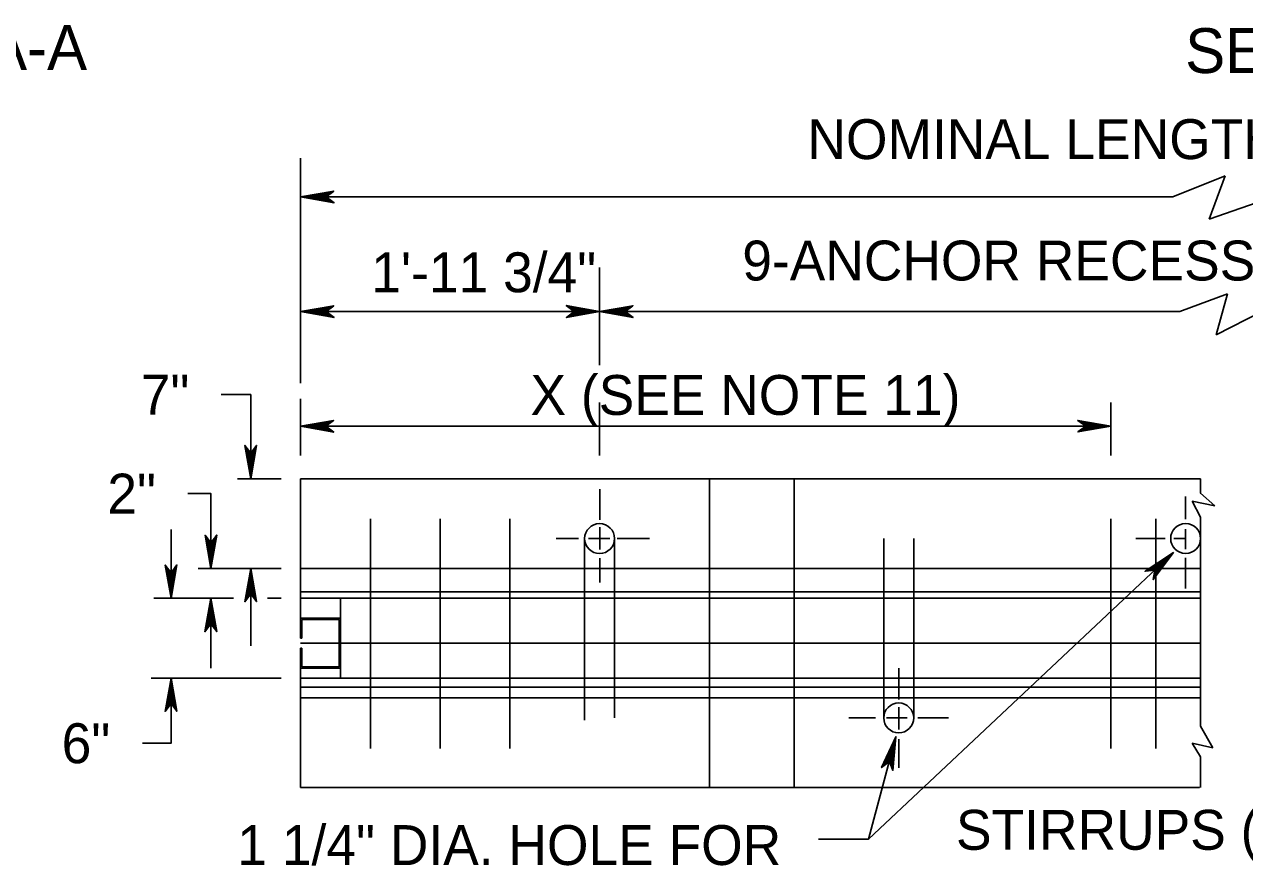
# Model space of a CAD drawing. Extents: x 499866 to 500993, y 499985 to 500645.
# Drawn here: x 500238.9 to 500361.2, y 500209.8 to 500294.1 of the extents above; entities that cross this region are included whole.
import ezdxf

# ---------------------------------------------------------------- set-up
doc = ezdxf.new("R2010")
doc.units = 0
doc.layers.add('24', color=7, linetype='Continuous')
doc.layers.add('5', color=7, linetype='Continuous')

msp = doc.modelspace()

# ---------------------------------------------------------------- linework, layer by layer
at = {"layer": '24'}
for points in [[(500266.6, 500276.85), (500269.95, 500276.25), (500269.15, 500276.85), (500269.93, 500277.43), (500266.6, 500276.85), (500266.82, 500276.85), (500269.85, 500276.3), (500269.09, 500276.85), (500269.8, 500277.38), (500266.94, 500276.86), (500267.05, 500276.85), (500269.65, 500276.38), (500269.07, 500276.85), (500269.67, 500277.31), (500267.1, 500276.85), (500267.21, 500276.86), (500269.49, 500276.45), (500269.04, 500276.85), (500269.5, 500277.25), (500267.54, 500276.86), (500267.73, 500276.86), (500269.32, 500276.54), (500269.01, 500276.84), (500269.34, 500277.17), (500267.76, 500276.85), (500267.94, 500276.84), (500269.14, 500276.63), (500268.91, 500276.86), (500269.16, 500277.09), (500268.1, 500276.85), (500268.27, 500276.83), (500268.99, 500276.69), (500268.87, 500276.85), (500269.07, 500277.03), (500268.36, 500276.85), (500268.83, 500276.73), (500268.76, 500276.86), (500268.97, 500276.99), (500268.48, 500276.86), (500268.79, 500276.79), (500268.66, 500276.89), (500268.8, 500276.95), (500268.66, 500276.85), (500268.73, 500276.84)], [(500266.6, 500265.35), (500269.95, 500264.75), (500269.15, 500265.35), (500269.93, 500265.93), (500266.6, 500265.35), (500266.82, 500265.35), (500269.85, 500264.8), (500269.09, 500265.35), (500269.8, 500265.88), (500266.94, 500265.36), (500267.05, 500265.35), (500269.65, 500264.88), (500269.07, 500265.35), (500269.67, 500265.81), (500267.1, 500265.35), (500267.21, 500265.36), (500269.49, 500264.95), (500269.04, 500265.35), (500269.5, 500265.75), (500267.54, 500265.36), (500267.73, 500265.36), (500269.32, 500265.04), (500269.01, 500265.34), (500269.34, 500265.67), (500267.76, 500265.35), (500267.94, 500265.34), (500269.14, 500265.13), (500268.91, 500265.36), (500269.16, 500265.59), (500268.1, 500265.35), (500268.27, 500265.33), (500268.99, 500265.19), (500268.87, 500265.35), (500269.07, 500265.53), (500268.36, 500265.35), (500268.83, 500265.23), (500268.76, 500265.36), (500268.97, 500265.49), (500268.48, 500265.36), (500268.79, 500265.29), (500268.66, 500265.39), (500268.8, 500265.45), (500268.66, 500265.35), (500268.73, 500265.34)], [(500296.57, 500265.35), (500293.22, 500265.94), (500294.02, 500265.35), (500293.24, 500264.76), (500296.57, 500265.35), (500296.35, 500265.34), (500293.31, 500265.89), (500294.08, 500265.34), (500293.37, 500264.81), (500296.23, 500265.33), (500296.11, 500265.35), (500293.52, 500265.81), (500294.1, 500265.34), (500293.5, 500264.88), (500296.06, 500265.35), (500295.95, 500265.33), (500293.68, 500265.74), (500294.12, 500265.35), (500293.67, 500264.94), (500295.63, 500265.33), (500295.44, 500265.33), (500293.85, 500265.66), (500294.16, 500265.36), (500293.83, 500265.02), (500295.41, 500265.35), (500295.23, 500265.36), (500294.03, 500265.56), (500294.26, 500265.33), (500294.01, 500265.1), (500295.06, 500265.35), (500294.89, 500265.36), (500294.18, 500265.5), (500294.29, 500265.34), (500294.1, 500265.16), (500294.81, 500265.35), (500294.34, 500265.46), (500294.41, 500265.33), (500294.2, 500265.2), (500294.69, 500265.33), (500294.38, 500265.41), (500294.51, 500265.31), (500294.36, 500265.24), (500294.51, 500265.34), (500294.43, 500265.36)], [(500296.57, 500265.35), (500299.92, 500264.75), (500299.12, 500265.35), (500299.9, 500265.93), (500296.57, 500265.35), (500296.79, 500265.35), (500299.83, 500264.8), (500299.06, 500265.35), (500299.77, 500265.88), (500296.91, 500265.36), (500297.02, 500265.35), (500299.62, 500264.88), (500299.04, 500265.35), (500299.64, 500265.81), (500297.07, 500265.35), (500297.19, 500265.36), (500299.46, 500264.95), (500299.02, 500265.35), (500299.47, 500265.75), (500297.51, 500265.36), (500297.7, 500265.36), (500299.29, 500265.04), (500298.98, 500265.34), (500299.31, 500265.67), (500297.73, 500265.35), (500297.91, 500265.34), (500299.11, 500265.13), (500298.88, 500265.36), (500299.13, 500265.59), (500298.07, 500265.35), (500298.24, 500265.33), (500298.96, 500265.19), (500298.84, 500265.35), (500299.04, 500265.53), (500298.33, 500265.35), (500298.8, 500265.23), (500298.73, 500265.36), (500298.94, 500265.49), (500298.45, 500265.36), (500298.76, 500265.29), (500298.63, 500265.39), (500298.78, 500265.45), (500298.63, 500265.35), (500298.71, 500265.34)], [(500266.6, 500253.85), (500269.92, 500253.26), (500269.13, 500253.85), (500269.91, 500254.42), (500266.6, 500253.85), (500266.82, 500253.85), (500269.83, 500253.3), (500269.07, 500253.85), (500269.77, 500254.38), (500266.94, 500253.86), (500267.05, 500253.85), (500269.63, 500253.39), (500269.05, 500253.85), (500269.64, 500254.3), (500267.1, 500253.85), (500267.21, 500253.86), (500269.46, 500253.46), (500269.03, 500253.85), (500269.47, 500254.25), (500267.53, 500253.86), (500267.72, 500253.86), (500269.3, 500253.54), (500268.99, 500253.84), (500269.32, 500254.17), (500267.75, 500253.85), (500267.93, 500253.84), (500269.12, 500253.63), (500268.89, 500253.86), (500269.14, 500254.09), (500268.09, 500253.85), (500268.26, 500253.83), (500268.97, 500253.69), (500268.86, 500253.85), (500269.05, 500254.03), (500268.35, 500253.85), (500268.81, 500253.74), (500268.74, 500253.86), (500268.95, 500253.99), (500268.46, 500253.86), (500268.77, 500253.79), (500268.64, 500253.89), (500268.79, 500253.95), (500268.64, 500253.85), (500268.72, 500253.84)], [(500347.82, 500253.85), (500344.49, 500254.43), (500345.29, 500253.85), (500344.51, 500253.27), (500347.82, 500253.85), (500347.59, 500253.84), (500344.58, 500254.39), (500345.35, 500253.84), (500344.64, 500253.31), (500347.48, 500253.83), (500347.37, 500253.85), (500344.79, 500254.3), (500345.37, 500253.84), (500344.77, 500253.39), (500347.31, 500253.85), (500347.2, 500253.83), (500344.95, 500254.24), (500345.39, 500253.85), (500344.94, 500253.44), (500346.88, 500253.83), (500346.7, 500253.83), (500345.12, 500254.15), (500345.42, 500253.86), (500345.09, 500253.52), (500346.66, 500253.85), (500346.48, 500253.86), (500345.3, 500254.06), (500345.53, 500253.83), (500345.28, 500253.6), (500346.32, 500253.85), (500346.15, 500253.86), (500345.44, 500254), (500345.56, 500253.84), (500345.36, 500253.66), (500346.07, 500253.85), (500345.6, 500253.96), (500345.67, 500253.83), (500345.47, 500253.7), (500345.95, 500253.83), (500345.65, 500253.91), (500345.77, 500253.81), (500345.63, 500253.75), (500345.77, 500253.84), (500345.7, 500253.86)], [(500261.6, 500248.58), (500262.19, 500251.93), (500261.6, 500251.13), (500261.02, 500251.92), (500261.6, 500248.58), (500261.6, 500248.81), (500262.15, 500251.84), (500261.59, 500251.07), (500261.06, 500251.78), (500261.59, 500248.93), (500261.6, 500249.04), (500262.06, 500251.64), (500261.6, 500251.05), (500261.14, 500251.65), (500261.6, 500249.09), (500261.59, 500249.2), (500262, 500251.47), (500261.6, 500251.03), (500261.19, 500251.48), (500261.58, 500249.52), (500261.59, 500249.71), (500261.91, 500251.3), (500261.61, 500250.99), (500261.28, 500251.33), (500261.6, 500249.75), (500261.61, 500249.92), (500261.82, 500251.12), (500261.58, 500250.89), (500261.36, 500251.14), (500261.6, 500250.09), (500261.62, 500250.26), (500261.76, 500250.98), (500261.59, 500250.86), (500261.42, 500251.05), (500261.6, 500250.35), (500261.71, 500250.81), (500261.59, 500250.75), (500261.46, 500250.95), (500261.58, 500250.46), (500261.66, 500250.77), (500261.56, 500250.64), (500261.5, 500250.79), (500261.59, 500250.64), (500261.61, 500250.72)], [(500257.61, 500239.59), (500258.2, 500242.94), (500257.61, 500242.14), (500257.02, 500242.92), (500257.61, 500239.59), (500257.6, 500239.81), (500258.15, 500242.85), (500257.6, 500242.08), (500257.07, 500242.79), (500257.59, 500239.93), (500257.61, 500240.04), (500258.07, 500242.64), (500257.6, 500242.06), (500257.14, 500242.66), (500257.61, 500240.1), (500257.59, 500240.21), (500258, 500242.48), (500257.61, 500242.04), (500257.2, 500242.49), (500257.59, 500240.53), (500257.59, 500240.72), (500257.91, 500242.31), (500257.61, 500242), (500257.28, 500242.33), (500257.61, 500240.75), (500257.62, 500240.93), (500257.82, 500242.13), (500257.59, 500241.9), (500257.36, 500242.15), (500257.61, 500241.1), (500257.62, 500241.26), (500257.76, 500241.98), (500257.6, 500241.86), (500257.42, 500242.06), (500257.61, 500241.35), (500257.72, 500241.82), (500257.59, 500241.75), (500257.46, 500241.96), (500257.59, 500241.47), (500257.67, 500241.78), (500257.56, 500241.65), (500257.5, 500241.8), (500257.6, 500241.65), (500257.61, 500241.73)], [(500354.09, 500241.17), (500351.25, 500239.31), (500352.23, 500239.43), (500352.06, 500238.47), (500354.09, 500241.17), (500353.93, 500241.02), (500351.34, 500239.34), (500352.28, 500239.47), (500352.13, 500238.59), (500353.85, 500240.93), (500353.76, 500240.86), (500351.55, 500239.42), (500352.3, 500239.48), (500352.17, 500238.74), (500353.72, 500240.83), (500353.65, 500240.74), (500351.72, 500239.48), (500352.31, 500239.5), (500352.26, 500238.89), (500353.42, 500240.52), (500353.28, 500240.39), (500351.9, 500239.54), (500352.33, 500239.53), (500352.31, 500239.06), (500353.25, 500240.38), (500353.11, 500240.26), (500352.1, 500239.59), (500352.42, 500239.58), (500352.4, 500239.24), (500353, 500240.14), (500352.86, 500240.04), (500352.24, 500239.65), (500352.44, 500239.61), (500352.42, 500239.35), (500352.81, 500239.97), (500352.39, 500239.73), (500352.53, 500239.68), (500352.47, 500239.45), (500352.73, 500239.88), (500352.46, 500239.72), (500352.62, 500239.74), (500352.55, 500239.59), (500352.6, 500239.76), (500352.53, 500239.72)], [(500253.61, 500236.59), (500254.2, 500239.94), (500253.61, 500239.14), (500253.03, 500239.92), (500253.61, 500236.59), (500253.6, 500236.81), (500254.16, 500239.85), (500253.6, 500239.08), (500253.07, 500239.79), (500253.59, 500236.93), (500253.61, 500237.05), (500254.07, 500239.65), (500253.6, 500239.06), (500253.15, 500239.66), (500253.61, 500237.1), (500253.59, 500237.21), (500254, 500239.48), (500253.61, 500239.04), (500253.2, 500239.49), (500253.59, 500237.53), (500253.59, 500237.72), (500253.92, 500239.31), (500253.62, 500239), (500253.28, 500239.34), (500253.61, 500237.75), (500253.62, 500237.93), (500253.82, 500239.13), (500253.59, 500238.9), (500253.36, 500239.15), (500253.61, 500238.1), (500253.63, 500238.27), (500253.76, 500238.99), (500253.6, 500238.87), (500253.42, 500239.06), (500253.61, 500238.35), (500253.72, 500238.82), (500253.59, 500238.75), (500253.46, 500238.96), (500253.59, 500238.47), (500253.67, 500238.78), (500253.57, 500238.65), (500253.51, 500238.8), (500253.6, 500238.65), (500253.62, 500238.73)], [(500261.6, 500239.59), (500261.01, 500236.24), (500261.6, 500237.04), (500262.19, 500236.26), (500261.6, 500239.59), (500261.61, 500239.37), (500261.05, 500236.33), (500261.61, 500237.1), (500262.14, 500236.39), (500261.62, 500239.25), (500261.6, 500239.14), (500261.14, 500236.54), (500261.61, 500237.12), (500262.06, 500236.52), (500261.6, 500239.08), (500261.62, 500238.97), (500261.21, 500236.7), (500261.6, 500237.14), (500262.01, 500236.69), (500261.62, 500238.65), (500261.62, 500238.46), (500261.29, 500236.87), (500261.59, 500237.18), (500261.93, 500236.85), (500261.6, 500238.43), (500261.59, 500238.25), (500261.39, 500237.05), (500261.62, 500237.28), (500261.85, 500237.03), (500261.6, 500238.08), (500261.58, 500237.92), (500261.45, 500237.2), (500261.61, 500237.32), (500261.79, 500237.12), (500261.6, 500237.83), (500261.49, 500237.36), (500261.62, 500237.43), (500261.75, 500237.22), (500261.62, 500237.71), (500261.54, 500237.4), (500261.64, 500237.53), (500261.7, 500237.38), (500261.61, 500237.53), (500261.59, 500237.45)], [(500257.61, 500236.59), (500257.01, 500233.24), (500257.61, 500234.04), (500258.19, 500233.26), (500257.61, 500236.59), (500257.61, 500236.37), (500257.06, 500233.34), (500257.61, 500234.1), (500258.14, 500233.39), (500257.62, 500236.25), (500257.61, 500236.14), (500257.14, 500233.54), (500257.61, 500234.12), (500258.07, 500233.52), (500257.61, 500236.09), (500257.62, 500235.98), (500257.21, 500233.7), (500257.61, 500234.15), (500258.01, 500233.69), (500257.62, 500235.65), (500257.62, 500235.46), (500257.3, 500233.87), (500257.6, 500234.18), (500257.93, 500233.85), (500257.61, 500235.43), (500257.59, 500235.25), (500257.39, 500234.05), (500257.62, 500234.28), (500257.85, 500234.04), (500257.61, 500235.09), (500257.59, 500234.92), (500257.45, 500234.2), (500257.61, 500234.32), (500257.79, 500234.12), (500257.61, 500234.83), (500257.49, 500234.36), (500257.62, 500234.43), (500257.75, 500234.22), (500257.62, 500234.71), (500257.55, 500234.4), (500257.65, 500234.53), (500257.71, 500234.39), (500257.61, 500234.53), (500257.6, 500234.46)], [(500253.61, 500228.6), (500253.02, 500225.25), (500253.61, 500226.05), (500254.19, 500225.27), (500253.61, 500228.6), (500253.61, 500228.38), (500253.06, 500225.34), (500253.62, 500226.11), (500254.15, 500225.4), (500253.62, 500228.26), (500253.61, 500228.14), (500253.15, 500225.55), (500253.62, 500226.13), (500254.07, 500225.53), (500253.61, 500228.09), (500253.62, 500227.98), (500253.21, 500225.71), (500253.61, 500226.15), (500254.02, 500225.7), (500253.63, 500227.66), (500253.62, 500227.47), (500253.3, 500225.88), (500253.6, 500226.19), (500253.93, 500225.85), (500253.61, 500227.44), (500253.6, 500227.26), (500253.39, 500226.06), (500253.63, 500226.29), (500253.85, 500226.04), (500253.61, 500227.09), (500253.59, 500226.92), (500253.45, 500226.21), (500253.62, 500226.32), (500253.79, 500226.13), (500253.61, 500226.84), (500253.5, 500226.37), (500253.62, 500226.44), (500253.75, 500226.23), (500253.63, 500226.72), (500253.55, 500226.41), (500253.65, 500226.54), (500253.71, 500226.39), (500253.62, 500226.54), (500253.6, 500226.46)], [(500326.27, 500222.71), (500324.83, 500219.62), (500325.61, 500220.24), (500325.97, 500219.34), (500326.27, 500222.71), (500326.22, 500222.49), (500324.9, 500219.7), (500325.64, 500220.3), (500325.96, 500219.48), (500326.2, 500222.37), (500326.16, 500222.27), (500325.04, 500219.88), (500325.64, 500220.32), (500325.92, 500219.62), (500326.14, 500222.22), (500326.13, 500222.11), (500325.15, 500220.02), (500325.64, 500220.34), (500325.92, 500219.8), (500326.05, 500221.79), (500326, 500221.61), (500325.27, 500220.16), (500325.64, 500220.38), (500325.88, 500219.97), (500325.97, 500221.58), (500325.92, 500221.41), (500325.41, 500220.31), (500325.69, 500220.47), (500325.85, 500220.17), (500325.88, 500221.25), (500325.82, 500221.09), (500325.51, 500220.44), (500325.69, 500220.51), (500325.81, 500220.27), (500325.82, 500221), (500325.59, 500220.58), (500325.73, 500220.61), (500325.8, 500220.38), (500325.8, 500220.89), (500325.65, 500220.61), (500325.78, 500220.71), (500325.8, 500220.55), (500325.75, 500220.72), (500325.71, 500220.65)]]:
    msp.add_lwpolyline(points, dxfattribs=at)
at = {"layer": '5'}
for p, q in [((500266.6, 500258.15), (500266.6, 500280.71)), ((500354.04, 500276.85), (500359.28, 500278.94)), ((500359.28, 500278.94), (500357.68, 500274.61)), ((500266.6, 500276.85), (500354.04, 500276.85)), ((500364.07, 500276.85), (500357.68, 500274.61)), ((500296.57, 500259.96), (500296.57, 500269.76)), ((500354.72, 500265.35), (500359.51, 500267.12)), ((500359.51, 500267.12), (500358.37, 500263.01)), ((500296.57, 500265.35), (500266.6, 500265.35)), ((500296.57, 500265.35), (500354.72, 500265.35)), ((500362.93, 500265.35), (500358.37, 500263.01)), ((500266.6, 500250.97), (500266.6, 500256.61)), ((500296.57, 500250.97), (500296.57, 500256.22)), ((500347.82, 500250.97), (500347.82, 500256.21)), ((500347.82, 500253.85), (500266.6, 500253.85)), ((500266.6, 500250.97), (500266.6, 500252.25)), ((500296.57, 500250.97), (500296.57, 500252.25)), ((500347.82, 500250.97), (500347.82, 500252.25)), ((500266.6, 500250.9), (500266.6, 500251.23)), ((500296.57, 500250.9), (500296.57, 500251.23)), ((500347.82, 500250.9), (500347.82, 500251.23)), ((500264.65, 500248.58), (500260.26, 500248.58)), ((500266.6, 500248.58), (500356.81, 500248.58)), ((500266.6, 500248.58), (500266.6, 500232.6)), ((500307.57, 500248.58), (500307.57, 500217.61)), ((500316.06, 500248.58), (500316.06, 500217.61)), ((500356.81, 500248.58), (500356.81, 500247.14)), ((500296.58, 500244.46), (500296.58, 500247.54)), ((500355.31, 500246.81), (500355.31, 500244.54)), ((500356.81, 500244.74), (500355.97, 500246.34)), ((500355.97, 500246.34), (500358.25, 500245.88)), ((500356.77, 500247.14), (500356.81, 500247.14)), ((500356.81, 500247.14), (500358.25, 500245.88)), ((500356.81, 500244.74), (500356.81, 500223.77)), ((500273.59, 500244.57), (500273.59, 500221.53)), ((500280.58, 500244.57), (500280.58, 500221.53)), ((500287.58, 500244.57), (500287.58, 500221.53)), ((500296.58, 500241.48), (500296.58, 500243.72)), ((500347.82, 500244.57), (500347.82, 500221.53)), ((500352.31, 500244.57), (500352.31, 500221.53)), ((500253.61, 500243.49), (500253.61, 500236.59)), ((500292.2, 500242.58), (500294.45, 500242.58)), ((500295.07, 500242.58), (500295.07, 500224.39)), ((500295.47, 500242.58), (500297.58, 500242.58)), ((500298.07, 500242.52), (500298.07, 500224.6)), ((500298.32, 500242.58), (500301.56, 500242.58)), ((500325.05, 500242.59), (500325.05, 500224.6)), ((500328.05, 500242.59), (500328.05, 500224.6)), ((500353.26, 500242.59), (500350.31, 500242.59)), ((500355.31, 500242.59), (500354.13, 500242.59)), ((500355.31, 500243.51), (500355.31, 500241.53)), ((500296.58, 500238.18), (500296.58, 500240.62)), ((500355.31, 500240.66), (500355.31, 500237.59)), ((500264.65, 500239.59), (500256.33, 500239.59)), ((500261.6, 500239.59), (500261.6, 500231.82)), ((500266.6, 500239.59), (500356.81, 500239.59)), ((500259.87, 500236.59), (500251.89, 500236.59)), ((500257.61, 500236.59), (500257.61, 500229.6)), ((500264.65, 500236.59), (500263.29, 500236.59)), ((500266.6, 500237.24), (500356.81, 500237.24)), ((500266.6, 500236.59), (500356.81, 500236.59)), ((500270.6, 500236.59), (500270.6, 500228.6)), ((500266.6, 500234.59), (500270.6, 500234.59)), ((500266.72, 500234.47), (500266.72, 500232.6)), ((500266.72, 500234.47), (500270.47, 500234.47)), ((500270.47, 500234.47), (500270.47, 500229.72)), ((500266.6, 500232.6), (500266.72, 500232.6)), ((500266.6, 500232.1), (500356.81, 500232.1)), ((500266.6, 500231.6), (500266.72, 500231.6)), ((500266.6, 500231.6), (500266.6, 500217.61)), ((500266.72, 500231.6), (500266.72, 500229.72)), ((500266.6, 500229.6), (500270.6, 500229.6)), ((500266.72, 500229.72), (500270.47, 500229.72)), ((500326.55, 500226.46), (500326.55, 500229.6)), ((500264.65, 500228.6), (500251.61, 500228.6)), ((500266.6, 500228.6), (500356.81, 500228.6)), ((500266.6, 500228.6), (500356.81, 500228.6)), ((500266.6, 500227.67), (500356.81, 500227.67)), ((500266.6, 500226.6), (500356.81, 500226.6)), ((500326.55, 500223.45), (500326.55, 500225.69)), ((500321.56, 500224.6), (500324.22, 500224.6)), ((500325.34, 500224.6), (500327.39, 500224.6)), ((500328.48, 500224.6), (500331.55, 500224.6)), ((500356.81, 500223.77), (500358.03, 500221.6)), ((500323.52, 500212.44), (500326.27, 500222.71)), ((500326.55, 500219.61), (500326.55, 500222.46)), ((500356.81, 500220.69), (500355.97, 500222.06)), ((500355.97, 500222.06), (500358.03, 500221.6)), ((500356.81, 500220.69), (500356.81, 500217.61)), ((500266.6, 500217.61), (500356.7, 500217.61))]:
    msp.add_line(p, q, dxfattribs=at)
for points in [[(500258.63, 500257.02), (500261.6, 500257.02), (500261.6, 500248.58)], [(500255.28, 500247.09), (500257.61, 500247.09), (500257.61, 500239.59)], [(500318.52, 500212.44), (500323.52, 500212.44), (500354.09, 500241.17)], [(500253.61, 500228.6), (500253.61, 500222.06), (500250.75, 500222.06)]]:
    msp.add_lwpolyline(points, dxfattribs=at)
for centre in [(500296.57, 500242.58), (500355.31, 500242.59), (500326.55, 500224.6)]:
    msp.add_circle(centre, 1.5, dxfattribs=at)

# ---------------------------------------------------------------- texts
for s, height, p in [('SECTION A-A', 4.5, (500206.75, 500289.57)), ('SECTION D-D', 4.5, (500355.26, 500289.26)), ('NOMINAL LENGTH', 4, (500317.4, 500280.63)), ('9-ANCHOR RECESSES AT 2\'-0" `', 4, (500310.87, 500268.46)), ('1\'-11 3/4"', 4, (500273.68, 500267.28)), ('7"', 4, (500250.58, 500255.02)), ('X (SEE NOTE 11)', 4, (500289.64, 500254.98)), ('2"', 4, (500247.23, 500245.09)), ('6"', 4, (500242.65, 500220.06)), ('STIRRUPS (TYPICAL)', 4, (500332.29, 500211.38)), ('1 1/4" DIA. HOLE FOR', 4, (500260.26, 500209.85))]:
    msp.add_text(s, height=height, dxfattribs=at).set_placement(p)

doc.saveas('drawing.dxf')
